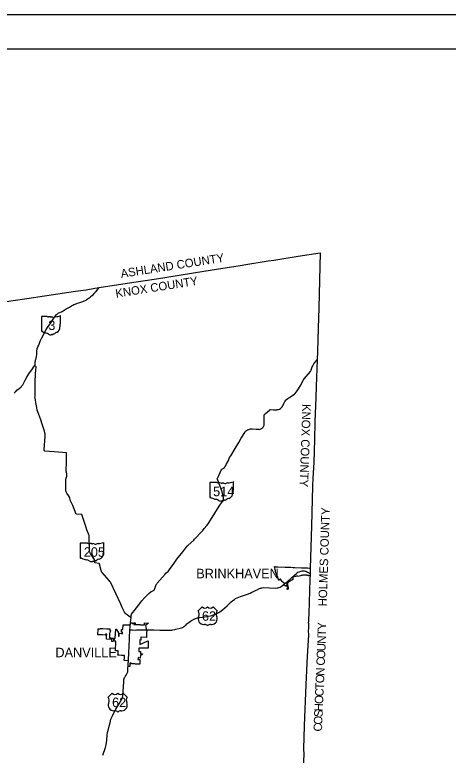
# Model space of a CAD drawing. Extents: x 1851937 to 2123937, y 78841 to 965467.
# Drawn here: x 2021685 to 2072811, y 878119 to 965467 of the extents above; entities that cross this region are included whole.
import ezdxf

# ---------------------------------------------------------------- set-up
doc = ezdxf.new("R2010")
doc.units = 0
for name, color, linetype in [('GM_X_Corporation', 7, 'Continuous'), ('GM_X_Corporation_Text', 7, 'Continuous'), ('GM_X_County', 7, 'Continuous'), ('GM_X_County_Text', 7, 'Continuous'), ('GM_X_State_Location', 7, 'Continuous'), ('GM_X_State_Route', 7, 'Continuous'), ('GM_X_State_Shield', 7, 'Continuous'), ('GM_X_US_Location', 7, 'Continuous'), ('GM_X_US_Route', 7, 'Continuous'), ('GM_X_US_Shield', 7, 'Continuous'), ('SH_Border', 7, 'Continuous'), ('SH_Cut_Line', 7, 'Continuous')]:
    doc.layers.add(name, color=color, linetype=linetype)

msp = doc.modelspace()

# ---------------------------------------------------------------- linework, layer by layer
at = {"layer": 'GM_X_Corporation'}
for points in [[(2052321, 900367), (2052352, 900365), (2052484, 900360), (2052703, 900351), (2053571, 900317), (2053588, 900316), (2053716, 900311), (2053718, 900311), (2053746, 900310), (2053776, 900308), (2053784, 900308), (2053794, 900308), (2053833, 900306), (2053913, 900303), (2053916, 900303), (2053922, 900303), (2053979, 900300), (2053982, 900300), (2053985, 900300), (2054057, 900297), (2054065, 900297), (2054208, 900291), (2054246, 900290), (2054254, 900289), (2054513, 900279), (2054719, 900271), (2055512, 900239), (2055579, 900236), (2055655, 900233), (2055792, 900228), (2055867, 900225), (2055883, 900224), (2055889, 900224), (2055898, 900224), (2056133, 900214), (2056231, 900210), (2056453, 900201), (2056542, 900198), (2056537, 900024), (2056536, 899999), (2056535, 899974), (2056531, 899854), (2056529, 899775), (2056527, 899731), (2056526, 899688), (2056521, 899532), (2056520, 899491), (2056518, 899449), (2056512, 899250), (2056449, 899275), (2056386, 899297), (2056322, 899318), (2056257, 899336), (2056192, 899352), (2056190, 899336), (2056124, 899344), (2056057, 899350), (2055991, 899354), (2055925, 899356), (2055858, 899355), (2055792, 899352), (2055725, 899347), (2055659, 899340), (2055593, 899330), (2055528, 899318), (2055463, 899304), (2055399, 899288), (2055056, 899194), (2055058, 899244), (2054915, 899249), (2054801, 899213), (2054787, 899208), (2054658, 899167), (2054613, 899153), (2054489, 899114), (2054480, 898818), (2054441, 898805), (2054403, 898791), (2054365, 898776), (2054328, 898759), (2054297, 898745), (2054267, 898729), (2054231, 898710), (2054195, 898689), (2054161, 898667), (2054127, 898644), (2054094, 898620), (2054061, 898595), (2054030, 898569), (2053948, 898500), (2053919, 898508), (2053907, 898478), (2053885, 898446), (2053856, 898402), (2053846, 898378), (2053843, 898356), (2053850, 898306), (2053858, 898247), (2053863, 898210), (2053870, 898159), (2053887, 898057), (2053887, 898049), (2053887, 898025), (2053891, 898012), (2053910, 897980), (2053920, 897957), (2053925, 897947), (2053936, 897910), (2053944, 897874), (2053940, 897830), (2053923, 897797), (2053836, 897665), (2053834, 897663), (2053834, 897665), (2053834, 897772), (2053871, 897827), (2053881, 897847), (2053883, 897871), (2053878, 897895), (2053869, 897923), (2053869, 897926), (2053857, 897952), (2053836, 897987), (2053834, 897993), (2053833, 898476), (2053803, 898430), (2053787, 898394), (2053785, 898375), (2053783, 898355), (2053790, 898298), (2053802, 898214), (2053807, 898174), (2053784, 898159), (2053630, 898057), (2053447, 898211), (2053404, 898175), (2053393, 898187), (2053354, 898232), (2053465, 898334), (2053519, 898381), (2053293, 898546), (2053228, 898622), (2053016, 898874), (2052995, 898899), (2052831, 898805), (2052815, 898748), (2052668, 899194), (2052651, 899230), (2052606, 899344), (2052547, 899468), (2052488, 899624), (2052470, 899674), (2052452, 899732), (2052431, 899865)], [(2032719, 893036), (2032769, 893034), (2032904, 893030), (2032902, 893000), (2032890, 892847), (2032956, 892844), (2032943, 892644), (2032878, 892647), (2032865, 892475), (2032855, 892325), (2032870, 892324), (2032857, 892145), (2032845, 891966), (2032987, 891957), (2033021, 891954), (2033163, 891945), (2033178, 891944), (2033318, 891935), (2033317, 891922), (2033308, 891786), (2033341, 891784), (2033441, 891778), (2033442, 891797), (2033447, 891917), (2033502, 891913), (2033542, 891911), (2033622, 892971), (2033624, 893001), (2033671, 892998), (2033688, 892967), (2033922, 892555), (2033902, 892168), (2034015, 892161), (2033987, 892497), (2034269, 892480), (2034268, 892459), (2034402, 892451), (2034408, 892586), (2034409, 892625), (2034275, 892630), (2034274, 892778), (2034273, 892936), (2034273, 892966), (2034397, 892959), (2034424, 892958), (2034480, 893517), (2034608, 893514), (2034801, 893509), (2035142, 893501), (2035273, 893498), (2035303, 893496), (2035305, 893514), (2035316, 893630), (2035318, 893655), (2035320, 893680), (2035327, 893754), (2035357, 893754), (2035466, 893752), (2035550, 893750), (2035546, 893649), (2035735, 893644), (2035739, 893746), (2035815, 893744), (2035886, 893743), (2035882, 893550), (2035808, 893551), (2035728, 893552), (2035726, 893528), (2035749, 893527), (2035807, 893527), (2035881, 893526), (2035986, 893525), (2036089, 893523), (2036228, 893522), (2036358, 893520), (2036362, 893520), (2036405, 893520), (2036446, 893519), (2036512, 893518), (2036578, 893518), (2036644, 893517), (2036710, 893516), (2036776, 893515), (2036792, 893515), (2036842, 893515), (2036849, 893514), (2036908, 893514), (2036974, 893513), (2036986, 893727), (2037426, 893698), (2037473, 893695), (2037114, 893431), (2037120, 893397), (2037144, 893235), (2037148, 893211), (2037148, 893207), (2037171, 893056), (2037190, 892934), (2037195, 892904), (2037246, 892904), (2037245, 892874), (2037236, 892509), (2037223, 892019), (2036593, 892025), (2036568, 892026), (2036555, 891698), (2036426, 891713), (2036418, 891193), (2037314, 891562), (2037408, 891601), (2037407, 891496), (2037406, 891434), (2037404, 891204), (2037402, 891068), (2037402, 890979), (2037401, 890944), (2037401, 890913), (2037403, 890884), (2037412, 890731), (2037245, 890736), (2037171, 890738), (2036917, 890746), (2036847, 890748), (2036581, 890760), (2036580, 890741), (2036573, 890741), (2036457, 890745), (2036396, 890747), (2036335, 890750), (2036331, 890645), (2036331, 890624), (2036330, 890603), (2036329, 890584), (2036329, 890569), (2036325, 890479), (2036325, 890463), (2036321, 890368), (2036320, 890338), (2036528, 890343), (2036504, 890073), (2036733, 890077), (2036724, 889977), (2036495, 889974), (2036458, 889565), (2036298, 889601), (2036242, 889625), (2036240, 889615), (2036239, 889607), (2036209, 889420), (2036254, 889418), (2036448, 889411), (2036442, 889276), (2036439, 889186), (2036436, 889126), (2036425, 888859), (2036239, 888865), (2036186, 888867), (2035915, 888876), (2035794, 888881), (2035713, 888883), (2035632, 888886), (2035521, 888890), (2035483, 888892), (2035448, 888893), (2035387, 889008), (2035269, 888982), (2035256, 888762), (2035245, 888577), (2035213, 888575), (2035076, 888569), (2035046, 888567), (2035056, 888752), (2035065, 888919), (2035066, 888938), (2035084, 889261), (2035058, 889262), (2035054, 889262), (2034599, 889287), (2034603, 889402), (2034608, 889557), (2034610, 889617), (2034612, 889692), (2034615, 889794), (2034618, 889883), (2034287, 889897), (2034004, 889909), (2033853, 889915), (2033854, 889932), (2033859, 890025), (2033860, 890044), (2033861, 890072), (2033865, 890143), (2033866, 890160), (2033867, 890176), (2033870, 890230), (2033880, 890413), (2033881, 890433), (2033560, 890447), (2033547, 890448), (2033602, 891460), (2033609, 891574), (2033470, 891583), (2033401, 891587), (2033391, 891588), (2033323, 891592), (2033312, 891593), (2033308, 891518), (2033272, 891520), (2033131, 891529), (2033134, 891604), (2033111, 891606), (2033113, 891642), (2033117, 891737), (2033119, 891767), (2033083, 891769), (2032499, 891806), (2032485, 891807), (2032487, 891837), (2032495, 891943), (2032498, 891987), (2032505, 892089), (2032511, 892166), (2032518, 892255), (2032524, 892344), (2032527, 892381), (2032376, 892389), (2032370, 892289), (2032007, 892301), (2031958, 892303), (2031464, 892319), (2031505, 893021), (2031760, 893013), (2031761, 893040), (2031763, 893070), (2032064, 893055), (2032532, 893041), (2032574, 893040), (2032640, 893038)]]:
    msp.add_lwpolyline(points, close=True, dxfattribs=at)
at = {"layer": 'GM_X_County'}
msp.add_lwpolyline([(2017735, 931206), (2023098, 932000), (2028854, 932870), (2030107, 933016), (2031110, 933200), (2031649, 933280), (2034948, 933801), (2038384, 934331), (2043974, 935218), (2046245, 935559), (2048555, 935947), (2048693, 935977), (2051562, 936437), (2052245, 936538), (2055094, 937003), (2057724, 937391), (2057545, 930886), (2057485, 928488), (2057387, 925735), (2057341, 924765), (2057236, 921624), (2057193, 920311), (2057098, 917443), (2057025, 915328), (2056946, 912676), (2056845, 910778), (2056821, 909883), (2056692, 905152), (2056529, 900191), (2056527, 900003), (2056520, 899740), (2056513, 899490), (2056492, 898858), (2056354, 894848), (2056334, 894166), (2056331, 894092), (2056325, 893939), (2056317, 893849), (2056312, 893777), (2056311, 893750), (2056318, 893677), (2056334, 893555), (2056336, 893469), (2056330, 893288), (2056319, 893081), (2056309, 892841), (2056314, 892278), (2056177, 889807), (2056002, 886440), (2055829, 881600), (2055757, 878860), (2055763, 878218), (2055528, 873511)], dxfattribs=at)
at = {"layer": 'GM_X_State_Route'}
for p, q in [((2029574, 906524), (2028910, 906536)), ((2035251, 892913), (2035278, 893241))]:
    msp.add_line(p, q, dxfattribs=at)
for points in [[(2031049, 932589), (2031119, 932678), (2031169, 932728), (2031225, 932786), (2031651, 933278)], [(2025077, 927735), (2025396, 928353), (2025530, 928568), (2025748, 928871), (2025934, 929145), (2026298, 929697), (2026469, 929952), (2026598, 930102), (2026670, 930162), (2026722, 930196), (2026799, 930249), (2027258, 930471), (2027751, 930766), (2028129, 930979), (2028379, 931133), (2028520, 931213), (2028651, 931276), (2028820, 931342), (2029076, 931428), (2029349, 931512), (2029713, 931654), (2029887, 931721), (2030084, 931814), (2030238, 931927), (2030572, 932159), (2030742, 932312), (2030911, 932447), (2031049, 932589)], [(2024506, 926484), (2024563, 926610), (2024693, 926970), (2024828, 927266), (2024877, 927367), (2025072, 927726), (2025077, 927735)], [(2024266, 925358), (2024275, 925520), (2024285, 925772), (2024294, 925888), (2024312, 925997), (2024339, 926107), (2024420, 926296), (2024506, 926484)], [(2024079, 924295), (2024091, 924454), (2024120, 924627), (2024142, 924729), (2024166, 924813), (2024178, 924861), (2024195, 924962), (2024225, 925154), (2024237, 925195), (2024266, 925358)], [(2023418, 923218), (2023467, 923286), (2023766, 923681), (2023902, 923882), (2024034, 924087), (2024060, 924131), (2024071, 924196), (2024079, 924295)], [(2053553, 919853), (2053564, 919874), (2053655, 919999), (2053741, 920091), (2053900, 920203), (2054126, 920351), (2054699, 920729), (2054777, 920789), (2054889, 920929), (2055003, 921089), (2055408, 921787), (2055703, 922344), (2055738, 922412), (2055816, 922525), (2056564, 923387), (2056606, 923460), (2056643, 923558), (2056731, 923835), (2056763, 923923), (2056834, 924072), (2056976, 924291), (2057097, 924461), (2057342, 924763)], [(2028910, 906536), (2028512, 907560), (2028248, 908130), (2028231, 908208), (2028214, 908286), (2028189, 908444), (2028185, 908462), (2028174, 908489), (2028140, 908564), (2028021, 908756), (2027822, 909043), (2027784, 909112), (2027745, 909197), (2027730, 909237), (2027716, 909287), (2027710, 909324), (2027706, 909359), (2027716, 910683), (2027747, 910800), (2027780, 910910), (2027816, 911014), (2027835, 911123), (2027829, 911187), (2027821, 911261), (2027783, 911525), (2027761, 911642), (2027758, 911816), (2027774, 912532), (2027798, 913358), (2027800, 913773), (2026334, 913904), (2025223, 913996), (2025197, 914012), (2025171, 914035), (2025159, 914050), (2025148, 914071), (2025144, 914093), (2025142, 914197), (2025247, 915720), (2025252, 915970), (2025249, 916031), (2025243, 916076), (2025232, 916134), (2025170, 916343), (2024920, 917178), (2024760, 917692), (2024397, 918645), (2024321, 918841), (2024296, 919139), (2024168, 919710), (2024114, 920041), (2024072, 920249), (2024065, 920338), (2024070, 920459), (2024072, 920586), (2024072, 921156), (2024093, 922294), (2024166, 923668), (2024188, 923818), (2024194, 923919), (2024189, 923955), (2024182, 923982), (2024130, 924023), (2024096, 924049), (2024034, 924087)], [(2021619, 920841), (2021725, 920964), (2021772, 921018), (2021836, 921085), (2021940, 921174), (2022214, 921395), (2022408, 921542), (2022484, 921610), (2022532, 921679), (2022622, 921819), (2022695, 921958), (2022897, 922355), (2023088, 922719), (2023347, 923120), (2023418, 923218)], [(2052386, 918870), (2052501, 918870), (2052612, 918867), (2052697, 918886), (2052790, 918910), (2052921, 918961), (2053042, 919035), (2053121, 919095), (2053188, 919163), (2053241, 919208), (2053314, 919342), (2053426, 919617), (2053542, 919833), (2053553, 919853)], [(2041489, 902130), (2041981, 902747), (2042022, 902806), (2042120, 902884), (2042796, 903479), (2042898, 903600), (2043788, 904564), (2043860, 904645), (2044025, 904847), (2044327, 905218), (2044494, 905414), (2044585, 905540), (2045297, 906690), (2045602, 907177), (2045886, 907615), (2046104, 907923), (2046209, 908079), (2046231, 908118), (2046271, 908222), (2046292, 908295), (2046310, 908377), (2046309, 908460), (2046299, 908535), (2046228, 908807), (2046140, 909185), (2046093, 909319), (2045920, 909811), (2045620, 910559), (2045584, 910637), (2045572, 910675), (2045569, 910693), (2045570, 910705), (2045577, 910728), (2045745, 911098), (2046085, 911820), (2046108, 911858), (2046174, 911909), (2046411, 912048), (2046472, 912120), (2046508, 912169), (2046576, 912304), (2046613, 912398), (2046877, 912891), (2047008, 913226), (2047153, 913443), (2047668, 914314), (2048101, 915027), (2048393, 915525), (2048805, 916203), (2048912, 916332), (2049129, 916493), (2049285, 916559), (2049380, 916587), (2049475, 916606), (2049552, 916610), (2049710, 916604), (2050146, 916587), (2050439, 916564), (2050533, 916561), (2050619, 916572), (2050780, 916644), (2050876, 916713), (2050937, 916765), (2050984, 916825), (2051026, 916890), (2051066, 916957), (2051088, 917043), (2051091, 917207), (2051083, 917637), (2051088, 918208), (2051111, 918283), (2051137, 918320), (2051248, 918418), (2051735, 918836), (2051785, 918870), (2051828, 918886), (2051868, 918886), (2052192, 918877), (2052386, 918870)], [(2031606, 900750), (2031170, 900815), (2031161, 900818), (2031153, 900823), (2031145, 900828), (2031138, 900837), (2031133, 900848), (2031128, 900865), (2031124, 900888), (2031091, 901195), (2030993, 901343), (2030607, 901899), (2030538, 902063), (2030515, 902159), (2030502, 902199), (2030486, 902283), (2030456, 904037), (2030412, 904181), (2030352, 904330), (2030186, 904712), (2030102, 904976), (2029574, 906524)], [(2035394, 894333), (2035401, 894372), (2035413, 894479), (2035431, 894627), (2035441, 894690), (2035464, 894765), (2035751, 895146), (2036305, 895851), (2036674, 896320), (2037033, 896738), (2037249, 896975), (2037503, 897207), (2037780, 897420), (2037883, 897481), (2037959, 897529), (2038107, 897604), (2038122, 897616), (2038137, 897633), (2038158, 897674), (2038194, 897796), (2038304, 898144), (2038365, 898262), (2038425, 898353), (2038490, 898429), (2039407, 899484), (2039498, 899587), (2039661, 899696), (2039771, 899804), (2039848, 899893), (2039939, 900024), (2040486, 900777), (2040801, 901265), (2041489, 902130)], [(2031882, 899866), (2031869, 899901), (2031691, 900670), (2031679, 900697), (2031668, 900711), (2031648, 900727), (2031606, 900750)], [(2035394, 894333), (2035342, 894353), (2034930, 894661), (2034814, 894748), (2034754, 894817), (2034645, 894996), (2034351, 895561), (2034180, 895951), (2033012, 898444), (2032972, 898530), (2032913, 898612), (2032828, 898722), (2031990, 899686), (2031926, 899764), (2031895, 899827), (2031882, 899866)], [(2035311, 893515), (2035313, 893532), (2035324, 893682), (2035330, 893731)], [(2035330, 893731), (2035369, 894074), (2035394, 894333)], [(2035278, 893241), (2035279, 893258), (2035301, 893431), (2035311, 893515)]]:
    msp.add_lwpolyline(points, dxfattribs=at)
at = {"layer": 'GM_X_State_Shield'}
for p, q in [((2024820, 929859), (2024820, 928158)), ((2025499, 929888), (2024842, 929888)), ((2027062, 929040), (2027062, 929930)), ((2027062, 929041), (2027062, 929040)), ((2044685, 910254), (2044685, 908553)), ((2045533, 910284), (2044712, 910284)), ((2047486, 909436), (2047486, 910326)), ((2047486, 909436), (2047486, 909436)), ((2032206, 902290), (2032206, 903180)), ((2029404, 903108), (2029404, 901407)), ((2030252, 903138), (2029432, 903138)), ((2032206, 902290), (2032206, 902290))]:
    msp.add_line(p, q, dxfattribs=at)
for centre, radius, start, end in [((2024846, 929862), 26, 98.1301, 188.1301), ((2025655, 930086), 252, 231.61951, 271.11188), ((2025739, 928933), 904, 80.48669, 94.98827), ((2025944, 929871), 72.7, 219.79206, 297.10237), ((2026051, 929675), 151, 54.46668, 119.14113), ((2026246, 929944), 182, 233.85621, 294.82819), ((2026567, 929369), 478, 97.34618, 120.76885), ((2026263, 932207), 2377, 275.84447, 288.90645), ((2027037, 929934), 25, 351.86209, 97.738), ((2026397, 928555), 595, 292.30889, 8.98584), ((2027151, 928668), 169, 136.8065, 186.92959), ((2027056, 928975), 38.6, 107.94398, 210.33697), ((2026810, 928863), 232, 340.03296, 23.64957), ((2027035, 929037), 26.7, 289.60381, 7.73413), ((2024846, 928154), 26.2, 171.95839, 258.30661), ((2024850, 928328), 200, 267.33899, 280.60386), ((2024891, 928060), 72.1, 29.74838, 93.27175), ((2025801, 929588), 1716, 240.41292, 257.1985), ((2025290, 927393), 537, 47.18416, 75.83597), ((2025870, 928051), 341, 230.70037, 286.29184), ((2026067, 927463), 280, 85.69512, 111.20995), ((2026092, 927924), 182, 268.77702, 315.54927), ((2026256, 927759), 51.1, 65.75173, 132.64842), ((2026235, 927993), 192, 282.87319, 323.27711), ((2026647, 927680), 326, 94.40312, 142.57675)]:
    msp.add_arc(centre, radius, start, end, dxfattribs=at)
for centre, major_axis, start_param, end_param in [((2044717, 910258), (32.5, 0), 1.712693, 3.28349), ((2045728, 910481), (315, 0), 4.042523, 4.731795), ((2045832, 909329), (1130, 0), 1.404758, 1.657858), ((2046089, 910267), (90.8, 0), 3.836095, 5.185415), ((2046222, 910070), (189, 0), 0.950623, 2.079405), ((2046466, 910340), (227, 0), 4.081561, 5.145723), ((2046867, 909764), (598, 0), 1.699011, 2.107814), ((2046488, 912603), (2971, 0), 4.814394, 5.042369), ((2047455, 910330), (31.2, 0), 6.141152, 7.989035), ((2047479, 909371), (48.3, 0), 1.883978, 3.671073), ((2047172, 909258), (290, 0), 5.934695, 6.695948), ((2047453, 909433), (33.4, 0), 5.05454, 6.418171), ((2044717, 908550), (32.7, 0), 3.00124, 4.508301), ((2044722, 908724), (250, 0), 4.665946, 4.897461), ((2044773, 908455), (90.1, 0), 0.519207, 1.627899), ((2045911, 909984), (2146, 0), 4.195997, 4.488961), ((2046655, 908950), (743, 0), 5.101752, 6.440018), ((2047598, 909064), (211, 0), 2.387724, 3.262537), ((2045271, 907789), (671, 0), 0.823519, 1.323587), ((2045997, 908447), (426, 0), 4.026481, 4.996735), ((2046243, 907859), (350, 0), 1.495662, 1.94098), ((2046274, 908319), (227, 0), 4.691044, 5.507374), ((2046480, 908155), (63.9, 0), 1.147584, 2.315152), ((2046452, 908388), (240, 0), 4.937069, 5.64225), ((2046968, 908076), (407, 0), 1.647645, 2.488434), ((2031208, 905457), (2971, 0), 4.814394, 5.042369), ((2032175, 903183), (31.2, 0), 6.141152, 7.989035), ((2029436, 903112), (32.5, 0), 1.712693, 3.28349), ((2030448, 903335), (315, 0), 4.042523, 4.731795), ((2030552, 902183), (1130, 0), 1.404758, 1.657858), ((2030809, 903121), (90.8, 0), 3.836095, 5.185415), ((2030942, 902924), (189, 0), 0.950623, 2.079405), ((2031186, 903194), (227, 0), 4.081561, 5.145723), ((2031587, 902618), (598, 0), 1.699011, 2.107814), ((2031374, 901804), (743, 0), 5.101752, 6.440018), ((2032318, 901917), (211, 0), 2.387724, 3.262537), ((2032199, 902224), (48.3, 0), 1.883978, 3.671073), ((2031892, 902112), (290, 0), 5.934695, 6.695948), ((2032173, 902286), (33.4, 0), 5.05454, 6.418171), ((2029437, 901403), (32.7, 0), 3.00124, 4.508301), ((2029441, 901577), (250, 0), 4.665946, 4.897461), ((2029493, 901309), (90.1, 0), 0.519207, 1.627899), ((2030630, 902837), (2146, 0), 4.195997, 4.488961), ((2029991, 900643), (671, 0), 0.823519, 1.323587), ((2030717, 901301), (426, 0), 4.026481, 4.996735), ((2030963, 900712), (350, 0), 1.495662, 1.94098), ((2030994, 901173), (227, 0), 4.691044, 5.507374), ((2031199, 901008), (63.9, 0), 1.147584, 2.315152), ((2031172, 901242), (240, 0), 4.937069, 5.64225), ((2031688, 900930), (407, 0), 1.647645, 2.488434)]:
    msp.add_ellipse(centre, major_axis=major_axis, ratio=0.8, start_param=start_param, end_param=end_param, dxfattribs=at)
at = {"layer": 'GM_X_US_Route'}
for p, q in [((2035245, 892598), (2035251, 892913)), ((2035251, 892913), (2035569, 892897)), ((2037108, 892901), (2037213, 892900)), ((2035063, 888891), (2035080, 889209))]:
    msp.add_line(p, q, dxfattribs=at)
for points in [[(2053508, 898334), (2053556, 898376), (2053848, 898629), (2054698, 899375), (2054912, 899561), (2055092, 899694), (2055238, 899770), (2055350, 899805), (2055476, 899840), (2055588, 899858), (2055720, 899857), (2055831, 899851), (2055941, 899832), (2056011, 899813), (2056094, 899784), (2056216, 899728), (2056313, 899665), (2056375, 899617), (2056440, 899563), (2056514, 899487)], [(2050382, 897692), (2050550, 897770), (2050649, 897810), (2050750, 897842), (2050817, 897858), (2051017, 897886), (2052435, 897839), (2052625, 897846), (2052739, 897860), (2052858, 897896), (2052994, 897946), (2053096, 898005), (2053371, 898216), (2053508, 898334)], [(2040021, 892874), (2040093, 892877), (2040204, 892886), (2040340, 892911), (2040581, 892967), (2040700, 892998), (2041345, 893134), (2041461, 893185), (2041580, 893249), (2041672, 893310), (2041753, 893374), (2041846, 893459), (2041989, 893600), (2042083, 893691), (2042238, 893810), (2042397, 893939), (2042531, 894022), (2042679, 894102), (2042839, 894180), (2042989, 894239), (2043135, 894291), (2043347, 894350), (2043493, 894378), (2044104, 894461), (2044346, 894480), (2044500, 894503), (2044761, 894555), (2044924, 894598), (2045190, 894701), (2045356, 894772), (2045596, 894887), (2045675, 894929), (2045747, 894969), (2045884, 895051), (2046040, 895152), (2046202, 895268), (2046729, 895741), (2046996, 895998), (2047222, 896207), (2047409, 896368), (2047585, 896496), (2047738, 896600), (2047907, 896693), (2048104, 896781), (2048291, 896855), (2049136, 897130), (2049444, 897249), (2049655, 897336), (2049779, 897396), (2050152, 897577), (2050354, 897679), (2050382, 897692)], [(2035569, 892897), (2035574, 892897), (2035888, 892887), (2036057, 892896), (2036256, 892906), (2036399, 892911), (2036420, 892911)], [(2036420, 892911), (2036509, 892912), (2036594, 892908), (2036897, 892903)], [(2036897, 892903), (2036908, 892902), (2037108, 892901)], [(2037213, 892900), (2037413, 892898), (2038078, 892894), (2038809, 892885), (2039708, 892875), (2039944, 892871), (2040021, 892874)], [(2035198, 891642), (2035199, 891668), (2035215, 891948), (2035234, 892265), (2035245, 892593), (2035245, 892598)], [(2035121, 890053), (2035142, 890365), (2035164, 890816), (2035185, 891185), (2035198, 891642)], [(2035080, 889209), (2035081, 889231), (2035098, 889530), (2035120, 890043), (2035121, 890053)], [(2032076, 878119), (2032379, 879016), (2032455, 879334), (2032530, 879874), (2032596, 880492), (2032632, 880804), (2032709, 881050), (2032822, 881524), (2032921, 881927), (2033019, 882363), (2033119, 882624), (2033197, 882778), (2033405, 883190), (2033534, 883406), (2033619, 883557), (2033985, 884196), (2034230, 884603), (2034355, 884826), (2034396, 884919), (2034428, 885076), (2034440, 885224), (2034480, 885675), (2034535, 886716), (2034563, 887049), (2034600, 887172), (2034645, 887282), (2034688, 887368), (2034728, 887432), (2034823, 887571), (2034910, 887716), (2034940, 887777), (2034978, 887866), (2035002, 887946), (2035011, 888009), (2035033, 888127), (2035035, 888308), (2035054, 888721), (2035063, 888891)]]:
    msp.add_lwpolyline(points, dxfattribs=at)
at = {"layer": 'GM_X_US_Shield'}
for p, q in [((2043781, 895610), (2043314, 895143)), ((2045556, 895143), (2045089, 895610)), ((2043968, 893555), (2044062, 893555)), ((2044809, 893555), (2044902, 893555)), ((2033176, 885424), (2032709, 884957)), ((2034951, 884957), (2034484, 885424)), ((2033363, 883370), (2033456, 883370)), ((2034203, 883370), (2034297, 883370))]:
    msp.add_line(p, q, dxfattribs=at)
for centre, radius, start, end in [((2044108, 895944), 467, 225.573, 314.427), ((2044762, 895944), 467, 225.573, 314.427), ((2043961, 894209), 654, 154.83192, 270.63826), ((2042779, 894768), 654, 334.54712, 35.00093), ((2044909, 894209), 654, 269.36174, 25.16808), ((2046091, 894768), 654, 144.99907, 205.45288), ((2044062, 893089), 467, 36.8699, 90), ((2044809, 893089), 467, 90, 143.1301), ((2032174, 884582), 654, 334.54712, 35.00093), ((2033503, 885758), 467, 225.573, 314.427), ((2034157, 885758), 467, 225.573, 314.427), ((2035486, 884582), 654, 144.99907, 205.45288), ((2033356, 884023), 654, 154.83192, 270.63826), ((2034304, 884023), 654, 269.36174, 25.16808), ((2033456, 882903), 467, 36.8699, 90), ((2034203, 882903), 467, 90, 143.1301)]:
    msp.add_arc(centre, radius, start, end, dxfattribs=at)
at = {"layer": 'SH_Border'}
msp.add_lwpolyline([(1863937, 961467), (2119937, 961467), (2119937, 793467), (1863937, 793467)], close=True, dxfattribs=at)
at = {"layer": 'SH_Cut_Line'}
msp.add_lwpolyline([(1851937, 789467), (2123937, 789467), (2123937, 965467), (1851937, 965467)], close=True, dxfattribs=at)

# ---------------------------------------------------------------- texts
at = {"layer": 'GM_X_Corporation_Text'}
for s, p in [('BRINKHAVEN', (2043090, 898992)), ('DANVILLE', (2026475, 889674))]:
    msp.add_text(s, height=1120, rotation=0.00001, dxfattribs=at).set_placement(p)
at = {"layer": 'GM_X_County_Text'}
for s, rotation, p in [('ASHLAND COUNTY', 8.93999, (2034250, 934426)), ('KNOX COUNTY', 8.99869, (2033643, 932083)), ('KNOX COUNTY', 268.08701, (2055609, 919565)), ('HOLMES COUNTY', 88.14145, (2058480, 895666)), ('Y', 89.57353, (2058405, 892914)), ('T', 88.80495, (2058389, 892152)), ('N', 87.87968, (2058356, 891250)), ('U', 87.63827, (2058319, 890362)), ('O', 87.55576, (2058281, 889477)), ('C', 87.53948, (2058246, 888663)), ('N', 87.53779, (2058195, 887476)), ('O', 87.53779, (2058157, 886593)), ('T', 87.53719, (2058125, 885845)), ('C', 87.53713, (2058090, 885032)), ('O', 87.53779, (2058052, 884148)), ('H', 87.53779, (2058014, 883265)), ('S', 87.53778, (2057985, 882588)), ('O', 87.53779, (2057947, 881704)), ('C', 87.53713, (2057912, 880891))]:
    msp.add_text(s, height=1000, rotation=rotation, dxfattribs=at).set_placement(p)
at = {"layer": 'GM_X_State_Location'}
for s, p in [('3', (2025919, 929157)), ('514', (2050735, 917779)), ('205', (2030433, 901838))]:
    msp.add_text(s, height=1, rotation=0.00001, dxfattribs=at).set_placement(p)
for s, p in [('s', (2026070, 929230)), ('r', (2026070, 929230)), ('s', (2051088, 917852)), ('r', (2051088, 917852)), ('s', (2030786, 901911)), ('r', (2030786, 901911))]:
    msp.add_text(s, height=1, dxfattribs=at).set_placement(p)
at = {"layer": 'GM_X_State_Shield'}
for s, height, p in [('3', 1121, (2025634, 928278)), ('514', 1120.7, (2045080, 908673)), ('205', 1120.7, (2029822, 901527))]:
    msp.add_text(s, height=height, dxfattribs=at).set_placement(p)
at = {"layer": 'GM_X_US_Location'}
for s, p in [('0', (2044839, 894512)), ('/', (2044839, 894512)), ('0', (2033830, 884133)), ('/', (2033830, 884133))]:
    msp.add_text(s, height=1, dxfattribs=at).set_placement(p)
for p in [(2044632, 894305), (2033623, 883926)]:
    msp.add_text('62', height=1, rotation=0.00001, dxfattribs=at).set_placement(p)
at = {"layer": 'GM_X_US_Shield'}
for p in [(2043766, 893976), (2033160, 883790)]:
    msp.add_text('62', height=1120.7, dxfattribs=at).set_placement(p)

doc.saveas('drawing.dxf')
